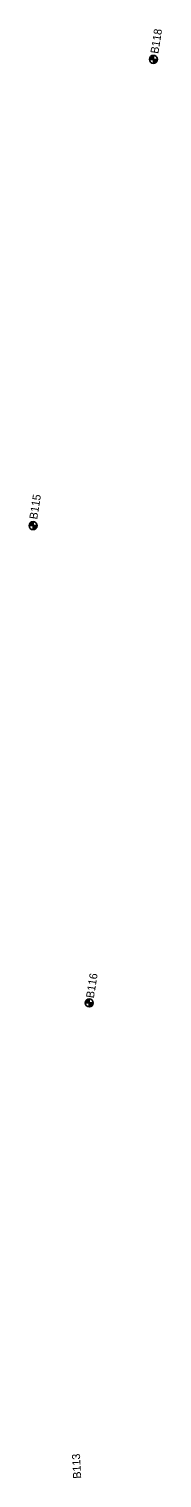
# Model space of a CAD drawing. Extents: x 335726 to 369746, y 119154 to 200788.
# Drawn here: x 355125 to 355291, y 191395 to 193207 of the extents above; entities that cross this region are included whole.
import ezdxf

# ---------------------------------------------------------------- set-up
doc = ezdxf.new("R2010")
doc.units = 0
for name, color, linetype in [('E_SOIL_BORE1 [KAPUR_CADDS_LEVELS]', 7, 'Continuous'), ('E_SOIL_BORE2 [KAPUR_CADDS_LEVELS]', 7, 'Continuous'), ('P_MARK', 7, 'Continuous')]:
    doc.layers.add(name, color=color, linetype=linetype)

msp = doc.modelspace()

# ---------------------------------------------------------------- linework, layer by layer
at = {"layer": 'P_MARK'}
for p, q in [((355275.6, 193168.8), (355285.6, 193168.8)), ((355280.6, 193173.8), (355280.6, 193163.8)), ((355125.2, 192585.9), (355135.2, 192585.9)), ((355130.2, 192590.9), (355130.2, 192580.9)), ((355195.5, 191989.3), (355205.5, 191989.3)), ((355200.5, 191994.3), (355200.5, 191984.3))]:
    msp.add_line(p, q, dxfattribs=at)
for centre in [(355280.6, 193168.8), (355130.2, 192585.9), (355200.5, 191989.3)]:
    msp.add_circle(centre, 5, dxfattribs=at)
for centre, radius, start, end in [((355280.6, 193168.8), 4.5, 89.9869, 179.9869), ((355280.6, 193168.8), 4, 89.9869, 179.9869), ((355280.6, 193168.8), 3.5, 89.9869, 179.9869), ((355280.6, 193168.8), 3, 89.9869, 179.9869), ((355280.6, 193168.8), 2.5, 89.9869, 179.9869), ((355280.6, 193168.8), 2, 89.9869, 179.9869), ((355280.6, 193168.8), 1.5, 89.9869, 179.9869), ((355280.6, 193168.8), 1, 89.9869, 179.9869), ((355280.6, 193168.8), 0.5, 89.9869, 179.9869), ((355280.6, 193168.8), 4.5, 269.9869, 359.9869), ((355280.6, 193168.8), 4, 269.9869, 359.9869), ((355280.6, 193168.8), 3.5, 269.9869, 359.9869), ((355280.6, 193168.8), 3, 269.9869, 359.9869), ((355280.6, 193168.8), 2.5, 269.9869, 359.9869), ((355280.6, 193168.8), 2, 269.9869, 359.9869), ((355280.6, 193168.8), 1.5, 269.9869, 359.9869), ((355280.6, 193168.8), 1, 269.9869, 359.9869), ((355280.6, 193168.8), 0.5, 269.9869, 359.9869), ((355130.2, 192585.9), 4.5, 89.9869, 179.9869), ((355130.2, 192585.9), 4, 89.9869, 179.9869), ((355130.2, 192585.9), 3.5, 89.9869, 179.9869), ((355130.2, 192585.9), 3, 89.9869, 179.9869), ((355130.2, 192585.9), 2.5, 89.9869, 179.9869), ((355130.2, 192585.9), 2, 89.9869, 179.9869), ((355130.2, 192585.9), 1.5, 89.9869, 179.9869), ((355130.2, 192585.9), 1, 89.9869, 179.9869), ((355130.2, 192585.9), 0.5, 89.9869, 179.9869), ((355130.2, 192585.9), 4.5, 269.9869, 359.9869), ((355130.2, 192585.9), 4, 269.9869, 359.9869), ((355130.2, 192585.9), 3.5, 269.9869, 359.9869), ((355130.2, 192585.9), 3, 269.9869, 359.9869), ((355130.2, 192585.9), 2.5, 269.9869, 359.9869), ((355130.2, 192585.9), 2, 269.9869, 359.9869), ((355130.2, 192585.9), 1.5, 269.9869, 359.9869), ((355130.2, 192585.9), 1, 269.9869, 359.9869), ((355130.2, 192585.9), 0.5, 269.9869, 359.9869), ((355200.5, 191989.3), 4.5, 89.9869, 179.9869), ((355200.5, 191989.3), 4, 89.9869, 179.9869), ((355200.5, 191989.3), 3.5, 89.9869, 179.9869), ((355200.5, 191989.3), 3, 89.9869, 179.9869), ((355200.5, 191989.3), 2.5, 89.9869, 179.9869), ((355200.5, 191989.3), 2, 89.9869, 179.9869), ((355200.5, 191989.3), 1.5, 89.9869, 179.9869), ((355200.5, 191989.3), 1, 89.9869, 179.9869), ((355200.5, 191989.3), 0.5, 89.9869, 179.9869), ((355200.5, 191989.3), 4.5, 269.9869, 359.9869), ((355200.5, 191989.3), 4, 269.9869, 359.9869), ((355200.5, 191989.3), 3.5, 269.9869, 359.9869), ((355200.5, 191989.3), 3, 269.9869, 359.9869), ((355200.5, 191989.3), 2.5, 269.9869, 359.9869), ((355200.5, 191989.3), 2, 269.9869, 359.9869), ((355200.5, 191989.3), 1.5, 269.9869, 359.9869), ((355200.5, 191989.3), 1, 269.9869, 359.9869), ((355200.5, 191989.3), 0.5, 269.9869, 359.9869)]:
    msp.add_arc(centre, radius, start, end, dxfattribs=at)

# ---------------------------------------------------------------- texts
at = {"layer": 'E_SOIL_BORE1 [KAPUR_CADDS_LEVELS]'}
for s, p in [('B118', (355286.6, 193175.3)), ('B115', (355135.3, 192593.3))]:
    msp.add_text(s, height=10, rotation=80.9358, dxfattribs=at).set_placement(p)
at = {"layer": 'E_SOIL_BORE2 [KAPUR_CADDS_LEVELS]'}
for s, rotation, p in [('B116', 80.9358, (355206.1, 191994.8)), ('B113', 93.0065, (355190.4, 191394.9))]:
    msp.add_text(s, height=10, rotation=rotation, dxfattribs=at).set_placement(p)

doc.saveas('drawing.dxf')
